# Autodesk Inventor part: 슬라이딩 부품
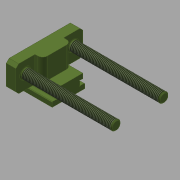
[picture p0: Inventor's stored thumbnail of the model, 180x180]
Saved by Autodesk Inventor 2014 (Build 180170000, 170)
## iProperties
Created: 2017-04
Part Number: 슬라이딩 부품
Material: 강철, 연강
Document SubType Name: Modeling
Designer: mduedu
Density: 7.86 g/cm^3
Appearance: 올리브 녹색
Mass: 395.304 g
Surface Area: 150.948 cm^2
Volume: 50.2931 cm^3
Author: mduedu
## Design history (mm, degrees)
sketch "스케치1"
  geometry: L1 (37, 35)-(10, 35); L2 (0, 17)-(0, 0); L3 (0, 17)-(5, 17); L4 (5, 17)-(5, 12); L5 (5, 12)-(10, 12); L6 (10, 12)-(10, 35); L7 (37, 35)-(37, 0); L8 (37, 0)-(0, 0); L9 (37, -35)-(10, -35); L10 (0, -17)-(0, 0); L11 (0, -17)-(5, -17); L12 (5, -17)-(5, -12); L13 (5, -12)-(10, -12); L14 (10, -12)-(10, -35); L15 (37, -35)-(37, 0)
  constraints: 30 end point, 6 symmetric about line, 3 perpendicular, 2 horizontal, 2 point on line, 2 vertical
  dimensions: "d39" = 5 distance of L2.start L3.end; "d41" = 70 distance between parallel lines of L9 L1; "d42" = 27 distance of L9.start L9.end; "d43" = 24 distance between parallel lines of L13 L5; "d44" = 5 distance of L4.end L5.end; "d45" = 34 distance between parallel lines of L11 L3
extrude "돌출1" new body sketch "스케치1" distance "d5" = 10; taper "d6" = 0 deg
sketch "스케치2"
  geometry: L1 (-35, 10)-(-35, 37) reference; L2 (17, 0)-(-17, 0) reference; L3 (-17, 0)-(-17, 5) reference; L4 (-17, 5)-(-12, 5) reference; L5 (-12, 5)-(-12, 10) reference; L6 (-12, 10)-(-35, 10) reference; L7 (-35, 37)-(35, 37) reference; L8 (35, 37)-(35, 10) reference; L9 (35, 10)-(12, 10) reference; L10 (12, 10)-(12, 5) reference; L11 (12, 5)-(17, 5) reference; L12 (17, 5)-(17, 0) reference; L13 (-12, 10)-(-15, 10); L14 (-15, 10)-(-15, 15); L15 (-15, 15)-(15, 15); L16 (15, 15)-(15, 10); L17 (15, 10)-(12, 10)
  constraints: 10 end point, 4 perpendicular, 2 point on line
  dimensions: "d46" = 3 distance between parallel lines of L14 L5; "d47" = 3 distance between parallel lines of L16 L10 (= d46); "d48" = 5 distance of L13.end L14.end
extrude "돌출2" join sketch "스케치2" distance "d12" = 20; taper "d13" = 0 deg
sketch "스케치3"
  geometry: L1 (0, 20)-(8, 20); L2 (8, 20)-(8, 50); L3 (8, 50)-(0, 50); L4 (0, 50)-(0, 20); L5 (0, 50)-(20, 50) reference; L6 (0, 20)-(20, 20) reference; L7 (0, 0)-(0, 70) reference; 2 further points
  constraints: 8 end point, 2 midpoint, 2 parallel, 1 horizontal, 1 perpendicular, 1 point on line
  dimensions: "d14" = 8 distance between parallel lines of L2 L4
extrude "돌출3" join sketch "스케치3" stored distance "d16" = 20; taper "d17" = 0 deg
fillet "모깎기1" dims "d18" = 5
sketch "스케치4"
  geometry: L1 (-15, 10)-(-35, 10) reference; L2 (-35, 10)-(-35, 37) reference; C1 r 5 at (-25, 25); 1 further point
  constraints: 1 centre point
  dimensions: "d19" = 10 diameter of C1; "d23" = 25 horizontal distance of point (0, 0) C1.centre (derived); "d49" = 15 distance from line of C1.centre L1; "d50" = 10 distance from line of C1.centre L2
extrude "돌출4" join sketch "스케치4" distance "d24" = 95; taper "d25" = 0 deg
feature "스레드1" dims "d26" = 10, "d27" = 0
chamfer "모따기1" distance "d28" = 1; stored, may be unused: second distance "d29" = 2, angle "d30" = 45 deg
fillet "모깎기2" dims "d31" = 1
sketch "스케치5"
  geometry: L1 (-12, 5)-(-12, 10) reference; L2 (12, 10)-(12, 5) reference; C1 r 0.5 at (-12, 10); C2 r 0.5 at (-12, 5); C3 r 0.5 at (12, 5); C4 r 0.5 at (12, 10); 1 further point
  constraints: 4 centre point, 4 coincident, 3 equal radius
  dimensions: "d51" = 1 diameter of C1
extrude "돌출5" cut sketch "스케치5" stored distance "d34" = 89; taper "d35" = 0 deg
chamfer "모따기2" distance "d36" = 3; stored, may be unused: second distance "d37" = 2, angle "d38" = 45 deg
chamfer "모따기3" distance "d52" = 0.5; stored, may be unused: second distance "d53" = 2, angle "d54" = 45 deg
mirror "대칭2"
node "솔리드2"
node "투영된 루프1"
node "솔리드1"
